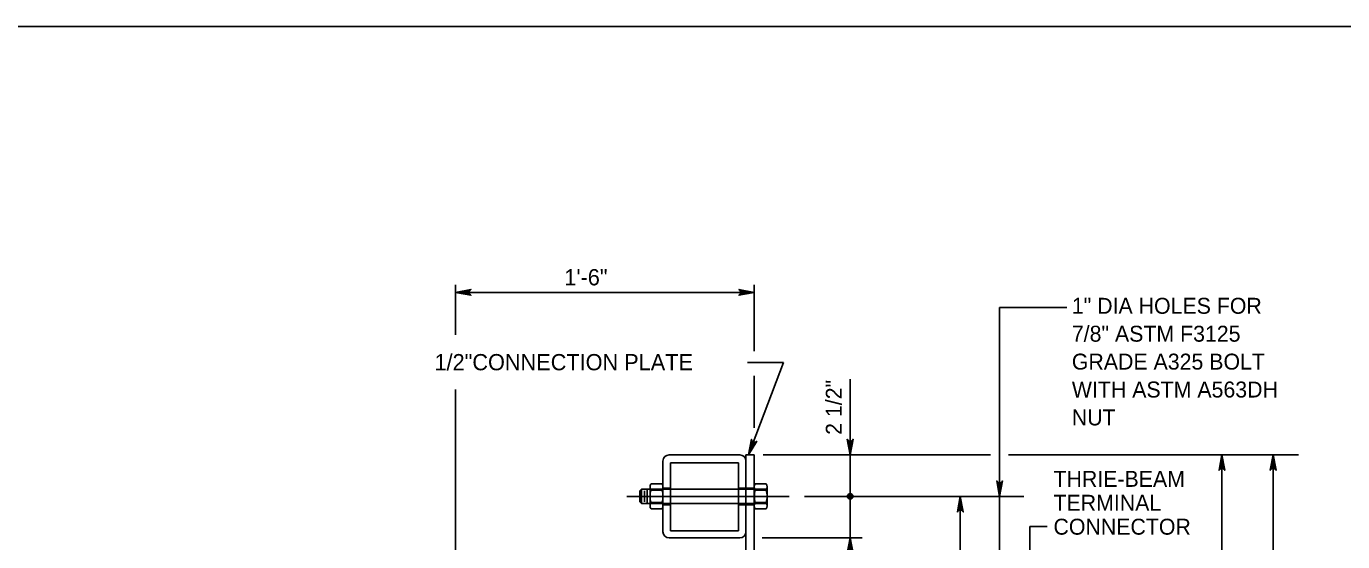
# Model space of a CAD drawing. Extents: x 632007860 to 635435983, y 295418622 to 297794622.
# Drawn here: x 633981587 to 634233315, y 296493131 to 296591622 of the extents above; entities that cross this region are included whole.
import ezdxf

# ---------------------------------------------------------------- set-up
doc = ezdxf.new("R2010")
doc.units = 0
for name, color, linetype in [('1', 7, 'Continuous'), ('8', 7, 'Continuous'), ('S-DETL-DIMS', 7, 'Continuous'), ('S-DETL-T120', 7, 'Continuous'), ('S-STEL', 7, 'Continuous')]:
    doc.layers.add(name, color=color, linetype=linetype)

msp = doc.modelspace()

# ---------------------------------------------------------------- linework, layer by layer
at = {"layer": '1'}
msp.add_line((633729860, 296591622), (634515860, 296591622), dxfattribs=at)
msp.add_line((633729860, 296591622), (634515860, 296591622), dxfattribs=at)
at = {"layer": '8'}
msp.add_line((634096395, 296501786), (634127477, 296501786), dxfattribs=at)
at = {"layer": 'S-DETL-DIMS'}
for p, q in [((634063650, 296542193), (634063650, 296532633)), ((634063650, 296540773), (634120801, 296540773)), ((634120800, 296542193), (634120800, 296529515)), ((634167713, 296428364), (634167713, 296537866)), ((634180540, 296537866), (634167713, 296537866)), ((634119506, 296527391), (634126401, 296527391)), ((634119701, 296509745), (634126401, 296527391)), ((634120800, 296524826), (634120800, 296514864)), ((634139138, 296480338), (634139138, 296524206)), ((634063650, 296522208), (634063650, 296441803)), ((634122520, 296509745), (634165943, 296509745)), ((634169412, 296509745), (634224878, 296509745)), ((634210223, 296385920), (634210223, 296509745)), ((634220031, 296385920), (634220031, 296509745)), ((634130404, 296501786), (634172314, 296501786)), ((634160194, 296385920), (634160194, 296501786)), ((634173509, 296496054), (634176787, 296496054)), ((634173509, 296478810), (634173509, 296496054)), ((634122294, 296493846), (634141457, 296493846))]:
    msp.add_line(p, q, dxfattribs=at)
for points in [[(634063650, 296540773), (634066610, 296541328), (634066496, 296541249), (634066382, 296541170), (634066323, 296541071), (634066264, 296540972), (634066247, 296540873), (634066230, 296540773), (634066247, 296540674), (634066264, 296540575), (634066323, 296540476), (634066382, 296540377), (634066496, 296540298), (634066610, 296540219), (634063650, 296540773), (634066496, 296540298), (634066382, 296540377), (634063650, 296540773), (634066323, 296540476), (634066264, 296540575), (634063650, 296540773), (634066247, 296540674), (634066230, 296540773), (634063650, 296540773), (634066247, 296540873), (634066264, 296540972), (634063650, 296540773), (634066323, 296541071), (634066382, 296541170), (634063650, 296540773), (634066496, 296541249)], [(634120801, 296540773), (634117842, 296540219), (634117956, 296540298), (634118070, 296540377), (634118128, 296540476), (634118187, 296540575), (634118204, 296540674), (634118221, 296540773), (634118204, 296540873), (634118187, 296540972), (634118128, 296541071), (634118070, 296541170), (634117956, 296541249), (634117842, 296541328), (634120801, 296540773), (634117956, 296541249), (634118070, 296541170), (634120801, 296540773), (634118128, 296541071), (634118187, 296540972), (634120801, 296540773), (634118204, 296540873), (634118221, 296540773), (634120801, 296540773), (634118204, 296540674), (634118187, 296540575), (634120801, 296540773), (634118128, 296540476), (634118070, 296540377), (634120801, 296540773), (634117956, 296540298)], [(634119701, 296509745), (634121270, 296512315), (634121156, 296512236), (634121041, 296512158), (634120928, 296512138), (634120814, 296512118), (634120715, 296512138), (634120617, 296512157), (634120530, 296512208), (634120443, 296512259), (634120371, 296512349), (634120299, 296512440), (634120266, 296512574), (634120233, 296512709), (634119701, 296509745), (634120266, 296512574), (634120299, 296512440), (634119701, 296509745), (634120371, 296512349), (634120443, 296512259), (634119701, 296509745), (634120530, 296512208), (634120617, 296512157), (634119701, 296509745), (634120715, 296512138), (634120814, 296512118), (634119701, 296509745), (634120928, 296512138), (634121041, 296512158), (634119701, 296509745), (634121156, 296512236)], [(634139138, 296509745), (634139693, 296512705), (634139614, 296512591), (634139535, 296512477), (634139435, 296512418), (634139336, 296512359), (634139237, 296512342), (634139138, 296512325), (634139039, 296512342), (634138939, 296512359), (634138840, 296512418), (634138741, 296512477), (634138662, 296512591), (634138583, 296512705), (634139138, 296509745), (634138662, 296512591), (634138741, 296512477), (634139138, 296509745), (634138840, 296512418), (634138939, 296512359), (634139138, 296509745), (634139039, 296512342), (634139138, 296512325), (634139138, 296509745), (634139237, 296512342), (634139336, 296512359), (634139138, 296509745), (634139435, 296512418), (634139535, 296512477), (634139138, 296509745), (634139614, 296512591)], [(634210223, 296509745), (634209669, 296506786), (634209748, 296506900), (634209827, 296507014), (634209926, 296507073), (634210025, 296507132), (634210124, 296507149), (634210223, 296507166), (634210323, 296507149), (634210422, 296507132), (634210521, 296507073), (634210620, 296507014), (634210699, 296506900), (634210778, 296506786), (634210223, 296509745), (634210699, 296506900), (634210620, 296507014), (634210223, 296509745), (634210521, 296507073), (634210422, 296507132), (634210223, 296509745), (634210323, 296507149), (634210223, 296507166), (634210223, 296509745), (634210124, 296507149), (634210025, 296507132), (634210223, 296509745), (634209926, 296507073), (634209827, 296507014), (634210223, 296509745), (634209748, 296506900)], [(634220031, 296509745), (634219476, 296506786), (634219555, 296506900), (634219634, 296507014), (634219733, 296507073), (634219833, 296507132), (634219932, 296507149), (634220031, 296507166), (634220130, 296507149), (634220230, 296507132), (634220329, 296507073), (634220428, 296507014), (634220507, 296506900), (634220586, 296506786), (634220031, 296509745), (634220507, 296506900), (634220428, 296507014), (634220031, 296509745), (634220329, 296507073), (634220230, 296507132), (634220031, 296509745), (634220130, 296507149), (634220031, 296507166), (634220031, 296509745), (634219932, 296507149), (634219833, 296507132), (634220031, 296509745), (634219733, 296507073), (634219634, 296507014), (634220031, 296509745), (634219555, 296506900)], [(634167713, 296501786), (634168268, 296504745), (634168189, 296504631), (634168110, 296504517), (634168010, 296504458), (634167911, 296504400), (634167812, 296504383), (634167713, 296504366), (634167614, 296504383), (634167514, 296504400), (634167415, 296504458), (634167316, 296504517), (634167237, 296504631), (634167158, 296504745), (634167713, 296501786), (634167237, 296504631), (634167316, 296504517), (634167713, 296501786), (634167415, 296504458), (634167514, 296504400), (634167713, 296501786), (634167614, 296504383), (634167713, 296504366), (634167713, 296501786), (634167812, 296504383), (634167911, 296504400), (634167713, 296501786), (634168010, 296504458), (634168110, 296504517), (634167713, 296501786), (634168189, 296504631)], [(634160194, 296501786), (634159640, 296498827), (634159719, 296498941), (634159798, 296499055), (634159897, 296499113), (634159996, 296499172), (634160095, 296499189), (634160194, 296499206), (634160294, 296499189), (634160393, 296499172), (634160492, 296499113), (634160591, 296499055), (634160670, 296498941), (634160749, 296498827), (634160194, 296501786), (634160670, 296498941), (634160591, 296499055), (634160194, 296501786), (634160492, 296499113), (634160393, 296499172), (634160194, 296501786), (634160294, 296499189), (634160194, 296499206), (634160194, 296501786), (634160095, 296499189), (634159996, 296499172), (634160194, 296501786), (634159897, 296499113), (634159798, 296499055), (634160194, 296501786), (634159719, 296498941)], [(634139138, 296493846), (634138583, 296490886)], [(634138741, 296491115), (634139138, 296493846), (634138662, 296491001)], [(634138939, 296491232), (634139138, 296493846), (634138840, 296491173)], [(634139138, 296491266), (634139138, 296493846), (634139039, 296491249)], [(634139693, 296490886), (634139138, 296493846), (634139614, 296491001)], [(634139535, 296491115), (634139138, 296493846), (634139435, 296491173)], [(634139336, 296491232), (634139138, 296493846), (634139237, 296491249)]]:
    msp.add_lwpolyline(points, dxfattribs=at)
for radius in [529, 265]:
    msp.add_circle((634139138, 296501786), radius, dxfattribs=at)
at = {"layer": 'S-STEL'}
for p, q in [((634103328, 296495033), (634103328, 296508535)), ((634104516, 296509722), (634118017, 296509722)), ((634104764, 296508219), (634117770, 296508219)), ((634104764, 296495213), (634104764, 296508219)), ((634117770, 296508219), (634117770, 296495213)), ((634119205, 296509745), (634120799, 296509745)), ((634119205, 296508535), (634119205, 296495033)), ((634119210, 296466991), (634119210, 296509745)), ((634120799, 296509745), (634120799, 296487444)), ((634099243, 296503175), (634098897, 296502828)), ((634098897, 296502828), (634098897, 296500747)), ((634099243, 296503175), (634100868, 296503175)), ((634099243, 296503175), (634099243, 296500400)), ((634099784, 296502828), (634099784, 296500747)), ((634100326, 296503175), (634100326, 296500400)), ((634100868, 296503587), (634100868, 296499985)), ((634104764, 296503175), (634100868, 296503175)), ((634103143, 296502989), (634101053, 296502989)), ((634103143, 296504189), (634101054, 296504189)), ((634103328, 296503587), (634103328, 296499985)), ((634103328, 296503375), (634104764, 296503375)), ((634104764, 296503175), (634117770, 296503175)), ((634117770, 296503375), (634120820, 296503375)), ((634117770, 296503175), (634120799, 296503175)), ((634120799, 296503587), (634120799, 296499985)), ((634120799, 296503175), (634123260, 296503175)), ((634120984, 296504189), (634123074, 296504189)), ((634120984, 296502989), (634123074, 296502989)), ((634123260, 296503587), (634123260, 296499985)), ((634098897, 296500747), (634099243, 296500400)), ((634099243, 296500400), (634100868, 296500400)), ((634104764, 296500400), (634100868, 296500400)), ((634103143, 296500585), (634101053, 296500585)), ((634103307, 296500197), (634104764, 296500197)), ((634104764, 296500400), (634117770, 296500400)), ((634117770, 296500400), (634120799, 296500400)), ((634117770, 296500197), (634120799, 296500197)), ((634120799, 296500400), (634123175, 296500400)), ((634120984, 296500585), (634123074, 296500585)), ((634103143, 296499384), (634101053, 296499384)), ((634120984, 296499384), (634123074, 296499384)), ((634117770, 296495213), (634104764, 296495213)), ((634118017, 296493846), (634104516, 296493846))]:
    msp.add_line(p, q, dxfattribs=at)
for centre, radius, start, end in [((634104516, 296508535), 1188, 90, 180), ((634118017, 296508535), 1188, 0, 90), ((634101934, 296503587), 1066, 145.7053, 214.2947), ((634104859, 296501787), 3991, 162.47188, 197.52812), ((634102262, 296503587), 1066, 325.7053, 34.2947), ((634099337, 296501787), 3991, 342.47188, 17.52812), ((634121865, 296503587), 1066, 145.7053, 214.2947), ((634124790, 296501787), 3991, 162.47188, 197.52812), ((634122194, 296503587), 1066, 325.7053, 34.2947), ((634119268, 296501787), 3991, 342.47188, 17.52812), ((634101934, 296499985), 1066, 145.7053, 214.2947), ((634102262, 296499985), 1066, 325.7053, 34.2947), ((634121865, 296499985), 1066, 145.7053, 214.2947), ((634122194, 296499985), 1066, 325.7053, 34.2947), ((634104516, 296495033), 1188, 180, 270), ((634118017, 296495033), 1188, 270, 0)]:
    msp.add_arc(centre, radius, start, end, dxfattribs=at)

# ---------------------------------------------------------------- texts
at = {"layer": 'S-DETL-T120'}
for s, height, p in [('1\'-6"', 3102.3, (634084474, 296542120)), ('1" DIA HOLES FOR', 3048.01, (634181524, 296536685)), ('7/8" ASTM F3125', 3048.01, (634181524, 296531351)), ('1/2"CONNECTION PLATE', 3102.3, (634059644, 296525885)), ('GRADE A325 BOLT', 3048.01, (634181524, 296526017)), ('WITH ASTM A563DH', 3048.01, (634181524, 296520683)), ('NUT', 3048, (634181524, 296515349)), ('THRIE-BEAM', 3048, (634178014, 296503609)), ('TERMINAL', 3048, (634178014, 296499037)), ('CONNECTOR', 3048, (634178014, 296494465))]:
    msp.add_text(s, height=height, dxfattribs=at).set_placement(p)
msp.add_text('2 1/2"', height=3048, rotation=90, dxfattribs=at).set_placement((634137524, 296513539))

doc.saveas('drawing.dxf')
